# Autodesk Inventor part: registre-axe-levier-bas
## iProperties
Author: chr
Created: 2001-06
Part Number: registre-axe-levier-bas
Material: Par défaut
Document SubType Name: Modélisation
Designer: chr
Control State: 0
Master: False
Checked Out: False
PropertySet Name: Design Tracking Control
Shininess: 20.0
PropertySet Name: _Private Model Information
Length Units: 11269
Angle Units: 11286
Time Units: 11279
Mass Units: 11290
Length Display Precision: 3
Angle Display Precision: 2
Compacted: False
Density: 0.0
Volumn: 0.0
Area: 0.0
PropertySet Name: Model Information
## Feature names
1. Extrusion1
2. Extrusion2
